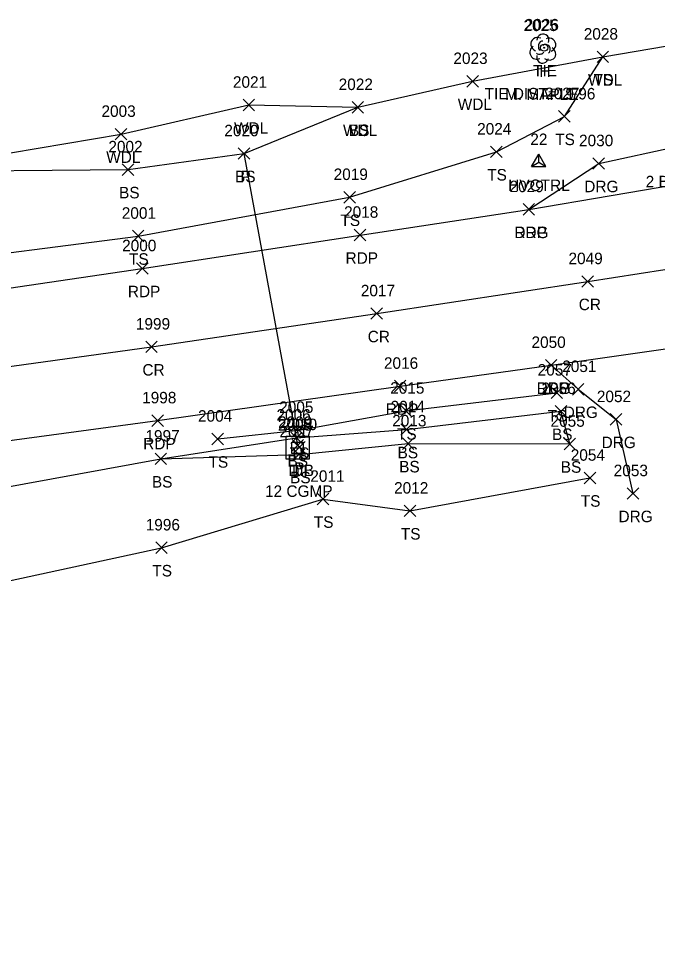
# Model space of a CAD drawing. Extents: x 1611797 to 1633212, y 298978 to 305475.
# Drawn here: x 1614264.5 to 1614375.5, y 301336.2 to 301499.6 of the extents above; entities that cross this region are included whole.
import ezdxf

# ---------------------------------------------------------------- set-up
doc = ezdxf.new("R2010")
doc.units = 0
for name, color, linetype in [('C_A', 7, 'Continuous'), ('C_C', 7, 'Continuous'), ('C_I', 7, 'Continuous'), ('CBP', 7, 'Continuous'), ('CPSM', 7, 'Continuous'), ('D_A', 7, 'Continuous'), ('D_C', 7, 'Continuous'), ('D_I', 7, 'Continuous'), ('D_TIC', 7, 'Continuous'), ('DCP', 7, 'Continuous'), ('DS', 7, 'Continuous'), ('L_A', 7, 'Continuous'), ('L_C', 7, 'Continuous'), ('L_I', 7, 'Continuous'), ('L_TIC', 7, 'Continuous'), ('LAWA', 7, 'Continuous'), ('LELB', 7, 'Continuous'), ('LTD', 7, 'Continuous'), ('P_A', 7, 'Continuous'), ('P_I', 7, 'Continuous'), ('P_TIC', 7, 'Continuous'), ('PET', 7, 'Continuous'), ('PRC', 7, 'Continuous'), ('R_A', 7, 'Continuous'), ('R_I', 7, 'Continuous'), ('R_TIC', 7, 'Continuous'), ('RDG', 7, 'Continuous')]:
    doc.layers.add(name, color=color, linetype=linetype)

msp = doc.modelspace()

# ---------------------------------------------------------------- linework, layer by layer
at = {"layer": 'CBP'}
for radius in [0.625, 0.0833]:
    msp.add_circle((1614355.85, 301494.58), radius, dxfattribs=at)
at = {"layer": 'CPSM'}
for p, q in [((1614353.65, 301473.92), (1614354.9, 301476.08)), ((1614356.15, 301473.92), (1614354.9, 301476.08)), ((1614354.91, 301474.64), (1614354.9, 301476.08)), ((1614353.65, 301473.92), (1614354.91, 301474.64)), ((1614353.65, 301473.92), (1614356.15, 301473.92)), ((1614354.91, 301474.64), (1614354.91, 301474.64)), ((1614354.91, 301474.64), (1614356.15, 301473.92))]:
    msp.add_line(p, q, dxfattribs=at)
at = {"layer": 'D_TIC'}
for points in [[(1614302.68, 301475.17), (1614304.68, 301477.17)], [(1614304.68, 301475.17), (1614302.68, 301477.17)], [(1614312.03, 301424.44), (1614314.03, 301426.44)], [(1614314.03, 301424.44), (1614312.03, 301426.44)], [(1614312.3, 301424.05), (1614314.3, 301426.05)], [(1614314.3, 301424.05), (1614312.3, 301426.05)]]:
    msp.add_lwpolyline(points, dxfattribs=at)
at = {"layer": 'DCP'}
msp.add_lwpolyline([(1614313.03, 301425.44), (1614303.68, 301476.17)], dxfattribs=at)
at = {"layer": 'DS'}
for p, q in [((1614310.98, 301426.98), (1614314.98, 301426.98)), ((1614310.98, 301422.98), (1614310.98, 301426.98)), ((1614314.98, 301426.98), (1614314.98, 301422.98)), ((1614311.98, 301423.98), (1614311.98, 301425.98)), ((1614311.98, 301425.98), (1614313.98, 301425.98)), ((1614312.98, 301424.98), (1614312.98, 301424.98)), ((1614312.98, 301424.98), (1614312.98, 301424.98)), ((1614313.98, 301425.98), (1614313.98, 301423.98)), ((1614313.98, 301423.98), (1614311.98, 301423.98)), ((1614314.98, 301422.98), (1614310.98, 301422.98))]:
    msp.add_line(p, q, dxfattribs=at)
at = {"layer": 'L_TIC'}
for points in [[(1614365.06, 301491.98), (1614367.06, 301493.98)], [(1614367.06, 301491.98), (1614365.06, 301493.98)], [(1614365.06, 301491.98), (1614367.06, 301493.98)], [(1614367.06, 301491.98), (1614365.06, 301493.98)], [(1614342.41, 301487.74), (1614344.41, 301489.74)], [(1614344.41, 301487.74), (1614342.41, 301489.74)], [(1614303.52, 301483.61), (1614305.52, 301485.61)], [(1614305.52, 301483.61), (1614303.52, 301485.61)], [(1614322.47, 301483.21), (1614324.47, 301485.21)], [(1614324.47, 301483.21), (1614322.47, 301485.21)], [(1614322.47, 301483.21), (1614324.47, 301485.21)], [(1614324.47, 301483.21), (1614322.47, 301485.21)], [(1614358.36, 301481.63), (1614360.36, 301483.63)], [(1614360.36, 301481.63), (1614358.36, 301483.63)], [(1614281.31, 301478.54), (1614283.31, 301480.54)], [(1614283.31, 301478.54), (1614281.31, 301480.54)], [(1614302.68, 301475.17), (1614304.68, 301477.17)], [(1614304.68, 301475.17), (1614302.68, 301477.17)], [(1614346.54, 301475.47), (1614348.54, 301477.47)], [(1614348.54, 301475.47), (1614346.54, 301477.47)], [(1614282.52, 301472.37), (1614284.52, 301474.37)], [(1614284.52, 301472.37), (1614282.52, 301474.37)], [(1614321.04, 301467.56), (1614323.04, 301469.56)], [(1614323.04, 301467.56), (1614321.04, 301469.56)], [(1614284.28, 301460.82), (1614286.28, 301462.82)], [(1614286.28, 301460.82), (1614284.28, 301462.82)], [(1614357.06, 301433.54), (1614359.06, 301435.54)], [(1614359.06, 301433.54), (1614357.06, 301435.54)], [(1614330.87, 301430.39), (1614332.87, 301432.39)], [(1614332.87, 301430.39), (1614330.87, 301432.39)], [(1614357.77, 301430.33), (1614359.77, 301432.33)], [(1614359.77, 301430.33), (1614357.77, 301432.33)], [(1614357.77, 301430.33), (1614359.77, 301432.33)], [(1614359.77, 301430.33), (1614357.77, 301432.33)], [(1614312.21, 301427.06), (1614314.21, 301429.06)], [(1614314.21, 301427.06), (1614312.21, 301429.06)], [(1614330.93, 301427.15), (1614332.93, 301429.15)], [(1614332.93, 301427.15), (1614330.93, 301429.15)], [(1614298.1, 301425.52), (1614300.1, 301427.52)], [(1614300.1, 301425.52), (1614298.1, 301427.52)], [(1614311.8, 301425.7), (1614313.8, 301427.7)], [(1614313.8, 301425.7), (1614311.8, 301427.7)], [(1614331.21, 301424.7), (1614333.21, 301426.7)], [(1614333.21, 301424.7), (1614331.21, 301426.7)], [(1614359.3, 301424.64), (1614361.3, 301426.64)], [(1614361.3, 301424.64), (1614359.3, 301426.64)], [(1614312.25, 301422.81), (1614314.25, 301424.81)], [(1614314.25, 301422.81), (1614312.25, 301424.81)], [(1614288.23, 301422.06), (1614290.23, 301424.06)], [(1614290.23, 301422.06), (1614288.23, 301424.06)], [(1614288.23, 301422.06), (1614290.23, 301424.06)], [(1614290.23, 301422.06), (1614288.23, 301424.06)], [(1614362.81, 301418.73), (1614364.81, 301420.73)], [(1614364.81, 301418.73), (1614362.81, 301420.73)], [(1614316.4, 301415.06), (1614318.4, 301417.06)], [(1614318.4, 301415.06), (1614316.4, 301417.06)], [(1614331.53, 301413.01), (1614333.53, 301415.01)], [(1614333.53, 301413.01), (1614331.53, 301415.01)], [(1614288.34, 301406.6), (1614290.34, 301408.6)], [(1614290.34, 301406.6), (1614288.34, 301408.6)]]:
    msp.add_lwpolyline(points, dxfattribs=at)
at = {"layer": 'LAWA'}
msp.add_lwpolyline([(1613659.39, 301379.3), (1613661.87, 301370.75), (1613686.93, 301375.42), (1613730.09, 301388.72), (1613768.03, 301396.97), (1613816.59, 301404.76), (1613861.02, 301415.83), (1613901.25, 301427.67), (1613950.68, 301436.07), (1613982.7, 301436.25), (1614021.38, 301440.86), (1614060.15, 301445.11), (1614098.09, 301453.38), (1614139.15, 301456.54), (1614173, 301459.52), (1614211.23, 301469.75), (1614243.82, 301473.03), (1614282.31, 301479.54), (1614304.52, 301484.61), (1614323.47, 301484.21), (1614343.41, 301488.74), (1614366.06, 301492.98), (1614391.26, 301497.25)], dxfattribs=at)
at = {"layer": 'LELB'}
for points in [[(1613688.22, 301363.65), (1613727.18, 301373.26), (1613772.17, 301382.86), (1613812.44, 301390.94), (1613866.01, 301400.43), (1613908.89, 301410.23), (1613926.88, 301414.84), (1613952.87, 301419.07), (1613986.36, 301422.88), (1614024.64, 301426.87), (1614063.32, 301431.77), (1614099.1, 301436.53), (1614140.8, 301441.18), (1614173.87, 301445.08), (1614214.29, 301453.13), (1614246.46, 301456.83), (1614285.28, 301461.82), (1614322.04, 301468.56), (1614347.54, 301476.47), (1614359.36, 301482.63), (1614366.06, 301492.98)], [(1613687.53, 301366.74), (1613727.39, 301378.05), (1613770.58, 301387.15), (1613814.37, 301395.8), (1613864.95, 301404.5), (1613892.63, 301410.62), (1613903.75, 301417.94), (1613926.3, 301423.14), (1613932.29, 301417.42), (1613937.13, 301418.44), (1613952.64, 301424.47), (1613985.55, 301430.21), (1614023.64, 301431.15), (1614062.6, 301434.14), (1614098.84, 301439.68), (1614140.09, 301444.03), (1614173.26, 301449.68), (1614212.1, 301463.73), (1614243.82, 301473.03), (1614283.52, 301473.37), (1614303.68, 301476.17), (1614323.47, 301484.21)], [(1614299.1, 301426.52), (1614313.21, 301428.06), (1614331.87, 301431.39), (1614358.06, 301434.54)], [(1614230.79, 301413.54), (1614251.17, 301416.09), (1614289.23, 301423.06), (1614312.8, 301426.7), (1614331.93, 301428.15), (1614358.77, 301431.33)], [(1614289.23, 301423.06), (1614313.25, 301423.81), (1614332.21, 301425.7), (1614360.3, 301425.64), (1614358.77, 301431.33)], [(1614232.47, 301407.22), (1614255.85, 301400.35), (1614289.34, 301407.6), (1614317.4, 301416.06), (1614332.53, 301414.01), (1614363.81, 301419.73)]]:
    msp.add_lwpolyline(points, dxfattribs=at)
at = {"layer": 'LTD'}
msp.add_line((1614355.6, 301494.47), (1614355.6, 301494.47), dxfattribs=at)
msp.add_line((1614355.6, 301494.47), (1614355.6, 301494.47), dxfattribs=at)
msp.add_arc((1614355.65, 301495.9), 1.05, 335.5272, 180.9563, dxfattribs=at)
for centre, major_axis, ratio, start_param, end_param in [((1614354.81, 301495.14), (1.21, -0.51), 0.895232, 1.570796, 4.712389), ((1614355.39, 301494.93), (-0.208, -0.792), 0.645439, 3.141593, 6.283185), ((1614356.1, 301494.3), (-0.5, 0.667), 0.989748, 3.141593, 6.283185), ((1614356.64, 301495.05), (-1.14, -0.48), 0.949671, 1.570796, 4.712389), ((1614354.52, 301493.76), (0.58, -1.04), 0.959034, 3.141593, 6.283185), ((1614355.14, 301493.72), (-0.625, -0.083), 0.423636, 0, 3.141593), ((1614356.6, 301493.64), (-1.09, 0.79), 0.841452, 1.570796, 4.712389), ((1614355.6, 301492.97), (0.26, 1.06), 0.942809, 1.570796, 4.712389)]:
    msp.add_ellipse(centre, major_axis=major_axis, ratio=ratio, start_param=start_param, end_param=end_param, dxfattribs=at)
at = {"layer": 'P_TIC'}
for points in [[(1614352.18, 301465.45), (1614354.18, 301467.45)], [(1614354.18, 301465.45), (1614352.18, 301467.45)], [(1614322.84, 301460.99), (1614324.84, 301462.99)], [(1614324.84, 301460.99), (1614322.84, 301462.99)], [(1614285, 301455.17), (1614287, 301457.17)], [(1614287, 301455.17), (1614285, 301457.17)], [(1614362.42, 301452.92), (1614364.42, 301454.92)], [(1614364.42, 301452.92), (1614362.42, 301454.92)], [(1614325.75, 301447.33), (1614327.75, 301449.33)], [(1614327.75, 301447.33), (1614325.75, 301449.33)], [(1614286.59, 301441.54), (1614288.59, 301443.54)], [(1614288.59, 301441.54), (1614286.59, 301443.54)], [(1614356.07, 301438.35), (1614358.07, 301440.35)], [(1614358.07, 301438.35), (1614356.07, 301440.35)], [(1614329.83, 301434.72), (1614331.83, 301436.72)], [(1614331.83, 301434.72), (1614329.83, 301436.72)], [(1614287.66, 301428.71), (1614289.66, 301430.71)], [(1614289.66, 301428.71), (1614287.66, 301430.71)]]:
    msp.add_lwpolyline(points, dxfattribs=at)
at = {"layer": 'PET'}
for points in [[(1613689.79, 301361.01), (1613727.87, 301369.49), (1613773.07, 301379.01), (1613813.19, 301387.7), (1613865.89, 301398.32), (1613909.58, 301406.72), (1613927.53, 301409.86), (1613953.4, 301414.17), (1613986.85, 301419.38), (1614025.22, 301424.34), (1614063.91, 301429.31), (1614099.06, 301433.16), (1614141.37, 301438.19), (1614174.31, 301441.58), (1614214.27, 301446.57), (1614246.62, 301450.37), (1614286, 301456.17), (1614323.84, 301461.99), (1614353.18, 301466.45), (1614396.11, 301473.72)], [(1613701.72, 301336.19), (1613728.29, 301342.74), (1613750.94, 301348.22), (1613776.31, 301353.3), (1613804.99, 301359.29), (1613841.24, 301366.59), (1613881.56, 301374.47), (1613915.09, 301380.99), (1613948.91, 301387.03), (1613987.44, 301392.91), (1614035.1, 301399.28), (1614067.29, 301403.16), (1614100.64, 301406.94), (1614145.48, 301411.71), (1614172.04, 301414.07), (1614174.91, 301413.62), (1614214.97, 301418.38), (1614220.25, 301418.94), (1614228.04, 301421.41), (1614249.59, 301424.45), (1614288.66, 301429.71), (1614330.83, 301435.72), (1614357.07, 301439.35), (1614396.41, 301445)]]:
    msp.add_lwpolyline(points, dxfattribs=at)
at = {"layer": 'PRC'}
msp.add_lwpolyline([(1613693.64, 301348.14), (1613730.35, 301356.23), (1613775.18, 301366.05), (1613815.88, 301374.59), (1613867.77, 301385.2), (1613911.17, 301393.09), (1613954.79, 301400.41), (1613984.71, 301404.65), (1614033.94, 301411.17), (1614065.91, 301415.23), (1614099.67, 301419.3), (1614143.88, 301424.7), (1614174.58, 301428.12), (1614215.56, 301433.27), (1614248.59, 301437.14), (1614287.59, 301442.54), (1614326.75, 301448.33), (1614363.42, 301453.92), (1614394.65, 301458.77)], dxfattribs=at)
at = {"layer": 'R_TIC'}
for points in [[(1614364.33, 301473.44), (1614366.33, 301475.44)], [(1614366.33, 301473.44), (1614364.33, 301475.44)], [(1614352.18, 301465.45), (1614354.18, 301467.45)], [(1614354.18, 301465.45), (1614352.18, 301467.45)], [(1614356.07, 301438.35), (1614358.07, 301440.35)], [(1614358.07, 301438.35), (1614356.07, 301440.35)], [(1614360.76, 301434.16), (1614362.76, 301436.16)], [(1614362.76, 301434.16), (1614360.76, 301436.16)], [(1614367.34, 301428.92), (1614369.34, 301430.92)], [(1614369.34, 301428.92), (1614367.34, 301430.92)], [(1614370.28, 301416.04), (1614372.28, 301418.04)], [(1614372.28, 301416.04), (1614370.28, 301418.04)]]:
    msp.add_lwpolyline(points, dxfattribs=at)
at = {"layer": 'RDG'}
for points in [[(1614353.18, 301466.45), (1614365.33, 301474.44), (1614379.22, 301477.45), (1614393.6, 301478.46), (1614432.71, 301479.37)], [(1614357.07, 301439.35), (1614361.76, 301435.16), (1614368.34, 301429.92), (1614371.28, 301417.04)]]:
    msp.add_lwpolyline(points, dxfattribs=at)

# ---------------------------------------------------------------- texts
at = {"layer": 'C_A'}
for s, p in [('TIE', (1614353.93, 301489.58)), ('HVCTRL', (1614349.6, 301469.64))]:
    msp.add_text(s, height=2, dxfattribs=at).set_placement(p)
at = {"layer": 'C_C'}
msp.add_text('TIE DIST=19.96', height=2, dxfattribs=at).set_placement((1614345.5, 301485.58))
at = {"layer": 'C_I'}
for s, p in [('2026', (1614352.46, 301497.58)), ('22', (1614353.44, 301477.64))]:
    msp.add_text(s, height=2, dxfattribs=at).set_placement(p)
at = {"layer": 'D_A'}
for s, p in [('P', (1614303.06, 301471.17)), ('DIB', (1614311.4, 301420.05)), ('DI', (1614312.04, 301419.98)), ('P', (1614312.41, 301420.44))]:
    msp.add_text(s, height=2, dxfattribs=at).set_placement(p)
at = {"layer": 'D_C'}
msp.add_text('12 CGMP', height=2, dxfattribs=at).set_placement((1614307.33, 301416.44))
at = {"layer": 'D_I'}
for s, p in [('2020', (1614300.26, 301479.17)), ('2008', (1614309.57, 301427.98)), ('2009', (1614309.61, 301428.44)), ('2010', (1614310.44, 301428.05))]:
    msp.add_text(s, height=2, dxfattribs=at).set_placement(p)
at = {"layer": 'L_A'}
for s, p in [('H', (1614355.03, 301489.47)), ('WDL', (1614363.48, 301487.98)), ('TS', (1614364.47, 301487.98)), ('WDL', (1614340.83, 301483.74)), ('WDL', (1614301.94, 301479.61)), ('WDL', (1614320.88, 301479.21)), ('BS', (1614321.91, 301479.21)), ('TS', (1614357.77, 301477.63)), ('WDL', (1614279.73, 301474.54)), ('BS', (1614302.12, 301471.17)), ('TS', (1614345.95, 301471.47)), ('BS', (1614281.96, 301468.37)), ('TS', (1614320.44, 301463.56)), ('TS', (1614283.69, 301456.82)), ('TS', (1614356.47, 301429.54)), ('TS', (1614330.27, 301426.39)), ('BS', (1614357.21, 301426.33)), ('BS', (1614357.21, 301426.33)), ('TS', (1614311.62, 301423.06)), ('BS', (1614330.37, 301423.15)), ('TS', (1614297.51, 301421.52)), ('BS', (1614311.24, 301421.7)), ('BS', (1614330.65, 301420.7)), ('BS', (1614358.74, 301420.64)), ('BS', (1614287.67, 301418.06)), ('BS', (1614287.67, 301418.06)), ('BS', (1614311.69, 301418.81)), ('TS', (1614362.22, 301414.73)), ('TS', (1614315.81, 301411.06)), ('TS', (1614330.94, 301409.01)), ('TS', (1614287.75, 301402.6))]:
    msp.add_text(s, height=2, dxfattribs=at).set_placement(p)
at = {"layer": 'L_C'}
for s, p in [('M. MAPLE', (1614349.05, 301485.47)), ('2 BOXES', (1614373.5, 301470.29))]:
    msp.add_text(s, height=2, dxfattribs=at).set_placement(p)
at = {"layer": 'L_I'}
for s, p in [('2025', (1614352.26, 301497.47)), ('2028', (1614362.73, 301495.98)), ('2028', (1614362.73, 301495.98)), ('2023', (1614340.07, 301491.74)), ('2021', (1614301.75, 301487.61)), ('2022', (1614320.13, 301487.21)), ('2022', (1614320.13, 301487.21)), ('2027', (1614356.02, 301485.63)), ('2003', (1614278.9, 301482.54)), ('2020', (1614300.26, 301479.17)), ('2024', (1614344.2, 301479.47)), ('2002', (1614280.1, 301476.37)), ('2019', (1614319.26, 301471.56)), ('2001', (1614282.43, 301464.82)), ('2057', (1614354.72, 301437.54)), ('2015', (1614329.09, 301434.39)), ('2056', (1614355.38, 301434.33)), ('2056', (1614355.38, 301434.33)), ('2005', (1614309.79, 301431.06)), ('2014', (1614329.16, 301431.15)), ('2004', (1614295.68, 301429.52)), ('2006', (1614309.32, 301429.7)), ('2013', (1614329.44, 301428.7)), ('2055', (1614356.96, 301428.64)), ('1997', (1614286.54, 301426.06)), ('1997', (1614286.54, 301426.06)), ('2007', (1614309.83, 301426.81)), ('2054', (1614360.47, 301422.73)), ('2011', (1614315.2, 301419.06)), ('2012', (1614329.76, 301417.01)), ('1996', (1614286.59, 301410.6))]:
    msp.add_text(s, height=2, dxfattribs=at).set_placement(p)
at = {"layer": 'P_A'}
for s, p in [('RDP', (1614350.67, 301461.45)), ('RDP', (1614321.33, 301456.99)), ('RDP', (1614283.49, 301451.17)), ('CR', (1614361.86, 301448.92)), ('CR', (1614325.18, 301443.33)), ('CR', (1614286.02, 301437.54)), ('RDP', (1614354.56, 301434.35)), ('RDP', (1614328.31, 301430.72)), ('RDP', (1614286.15, 301424.71))]:
    msp.add_text(s, height=2, dxfattribs=at).set_placement(p)
at = {"layer": 'P_I'}
for s, p in [('2029', (1614349.84, 301469.45)), ('2018', (1614321.07, 301464.99)), ('2000', (1614282.49, 301459.17)), ('2049', (1614360.08, 301456.92)), ('2017', (1614323.98, 301451.33)), ('1999', (1614284.88, 301445.54)), ('2050', (1614353.65, 301442.35)), ('2016', (1614328, 301438.72)), ('1998', (1614285.97, 301432.71))]:
    msp.add_text(s, height=2, dxfattribs=at).set_placement(p)
at = {"layer": 'R_A'}
for p in [(1614362.82, 301469.44), (1614350.67, 301461.45), (1614354.56, 301434.35), (1614359.25, 301430.16), (1614365.83, 301424.92), (1614368.77, 301412.04)]:
    msp.add_text('DRG', height=2, dxfattribs=at).set_placement(p)
at = {"layer": 'R_I'}
for s, p in [('2030', (1614361.91, 301477.44)), ('2029', (1614349.84, 301469.45)), ('2050', (1614353.65, 301442.35)), ('2051', (1614358.99, 301438.16)), ('2052', (1614365.01, 301432.92)), ('2053', (1614367.94, 301420.04))]:
    msp.add_text(s, height=2, dxfattribs=at).set_placement(p)

doc.saveas('drawing.dxf')
